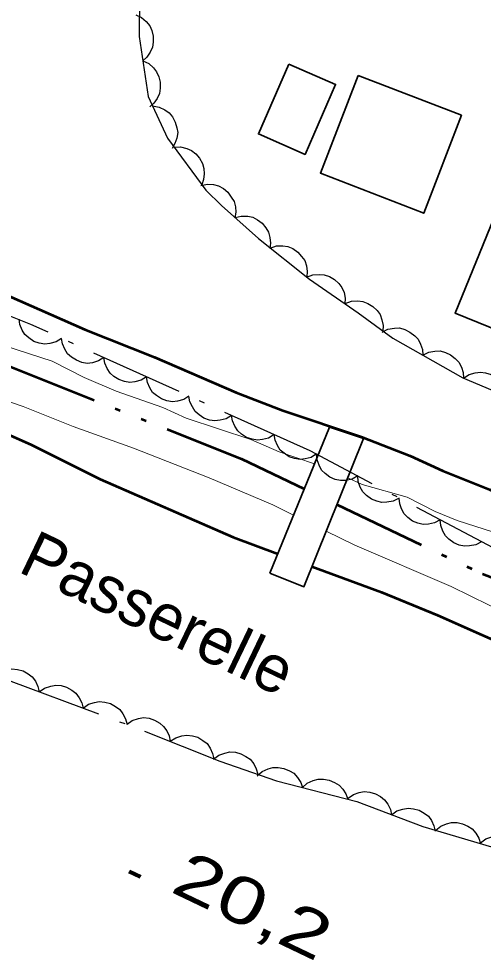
# Model space of a CAD drawing. Extents: x 355726 to 357533, y 5103782 to 5105258.
# Drawn here: x 356605.89 to 356620.8, y 5104468.41 to 5104498.68 of the extents above; entities that cross this region are included whole.
import ezdxf

# ---------------------------------------------------------------- set-up
doc = ezdxf.new("R2010")
doc.units = 0
doc.header["$LTSCALE"] = 0.6
for name, pattern in [('DASH_DOUBLE_DOT', [9.2, 5, -1.2, 0.3, -1.2, 0.3, -1.2]), ('DOT_DASHED', [7.7, 5, -1.2, 0.3, -1.2]), ('LONG_DASHED', [7.5, 6, -1.5])]:
    doc.linetypes.add(name, pattern=pattern)
for name, color, linetype, lineweight in [('1', 7, 'LONG_DASHED', 53), ('2', 7, 'LONG_DASHED', 13), ('26', 7, 'Continuous', 35), ('3', 7, 'Continuous', 140), ('31', 7, 'Continuous', 35), ('4', 7, 'DASH_DOUBLE_DOT', 53), ('44', 7, 'Continuous', 25)]:
    doc.layers.add(name, color=color, linetype=linetype, lineweight=lineweight)

msp = doc.modelspace()

# ---------------------------------------------------------------- linework, layer by layer
at = {"layer": '1', "linetype": 'Continuous'}
for points in [[(356552.78, 5104505.88), (356555.14, 5104504.63), (356555.86, 5104504.34), (356557.38, 5104503.83), (356561.34, 5104502.15), (356564.46, 5104500.97), (356566.07, 5104500.53), (356569.39, 5104499.78), (356570.17, 5104499.58), (356570.87, 5104499.33), (356577.95, 5104496.47), (356580.34, 5104495.65), (356581.96, 5104494.98), (356585.38, 5104493.8), (356587.71, 5104492.76), (356592.19, 5104491.03), (356593.74, 5104490.24), (356595.31, 5104489.51), (356599.4, 5104487.95), (356603.9, 5104486.04), (356606.29, 5104484.98), (356608.5, 5104483.88), (356612.77, 5104482.01), (356614.2, 5104481.48)], [(356586.93, 5104499.7), (356588.36, 5104498.47), (356588.88, 5104498.09), (356591.47, 5104496.68), (356592.2, 5104496.3), (356594.77, 5104495.21), (356597.27, 5104493.88), (356599.92, 5104492.26), (356601.23, 5104491.59), (356604.81, 5104490.09), (356608, 5104488.69), (356610.24, 5104487.8), (356612.87, 5104486.66), (356614.37, 5104486.09)], [(356614.37, 5104486.09), (356616.89, 5104485.24), (356618.46, 5104484.63), (356619.5, 5104484.15), (356621, 5104483.55), (356622.78, 5104482.71)], [(356615.3, 5104481.07), (356617.53, 5104480.24), (356619.33, 5104479.5), (356622.28, 5104478.2), (356623.46, 5104477.61), (356624.92, 5104477), (356626.48, 5104476.13), (356627.3, 5104475.49), (356627.64, 5104475.04), (356627.73, 5104474.76), (356627.72, 5104474.43), (356627.49, 5104473.61), (356626.72, 5104472.08), (356625.59, 5104470.34), (356624.65, 5104469.2), (356624.11, 5104468.62), (356622.87, 5104467.42)]]:
    msp.add_lwpolyline(points, dxfattribs=at)
at = {"layer": '2'}
for points in [[(356615.38, 5104484.37), (356614.25, 5104484.76), (356613.34, 5104485.15), (356611.26, 5104485.84), (356610.51, 5104486.18), (356609.01, 5104486.71), (356607.98, 5104487.15), (356606.96, 5104487.67), (356605.43, 5104488.16), (356603.34, 5104489.12), (356601.96, 5104489.84), (356600.44, 5104490.46), (356599.22, 5104491.03), (356595.18, 5104492.55), (356592.21, 5104494.03), (356589.05, 5104495.28), (356588.17, 5104495.73), (356587.25, 5104496.13)], [(356650.58, 5104495.13), (356648.88, 5104493.63), (356645.97, 5104491.47), (356644.47, 5104490.51), (356643.06, 5104489.53), (356637.5, 5104484.88), (356636.97, 5104484), (356636.63, 5104481.55), (356636.19, 5104480.2), (356635.05, 5104478.25), (356632.25, 5104477.67), (356629.29, 5104479.15), (356628.01, 5104479.68), (356624.56, 5104480.93), (356623.53, 5104481.26), (356621.13, 5104482.17), (356619.97, 5104482.55), (356619.26, 5104482.84), (356618.36, 5104483.3), (356616.91, 5104483.71), (356616.45, 5104483.92)]]:
    msp.add_lwpolyline(points, dxfattribs=at)
at = {"layer": '2', "linetype": 'Continuous'}
for points in [[(356586.39, 5104494.74), (356587.58, 5104494.49), (356588.54, 5104494.21), (356589.2, 5104493.95), (356589.86, 5104493.67), (356591.52, 5104492.84), (356592.94, 5104492.24), (356596.17, 5104490.57), (356598.1, 5104489.63), (356599.96, 5104488.82), (356603.26, 5104487.26), (356604.64, 5104486.69), (356606.02, 5104486.22), (356607.63, 5104485.57), (356609.57, 5104484.88), (356612, 5104483.92), (356614.04, 5104483.05), (356614.71, 5104482.72)], [(356615.76, 5104482.21), (356616.68, 5104481.76), (356619.77, 5104480.43), (356621.6, 5104479.53), (356624.34, 5104478.37), (356626.74, 5104477.11)]]:
    msp.add_lwpolyline(points, dxfattribs=at)
at = {"layer": '26'}
msp.add_lwpolyline([(356613.95, 5104480.86), (356615.86, 5104485.55), (356616.96, 5104485.19), (356615.04, 5104480.42)], close=True, dxfattribs=at)
at = {"layer": '3'}
msp.add_line((356609.43, 5104471.26), (356609.79, 5104471.09), dxfattribs=at)
at = {"layer": '31'}
for points in [[(356614.56, 5104497.22), (356613.58, 5104494.98), (356615.08, 5104494.32), (356616.06, 5104496.57), (356614.56, 5104497.22)], [(356616.78, 5104496.86), (356615.57, 5104493.72), (356618.89, 5104492.43), (356620.1, 5104495.58), (356616.78, 5104496.86)], [(356627.61, 5104493.8), (356624.91, 5104487.18), (356619.9, 5104489.22), (356622.6, 5104495.84), (356627.61, 5104493.8)]]:
    msp.add_lwpolyline(points, close=True, dxfattribs=at)
at = {"layer": '4'}
for points in [[(356565.46, 5104503.29), (356570.55, 5104501.29), (356578.56, 5104498.65), (356585.95, 5104495.66), (356595.51, 5104491.86), (356605.52, 5104487.53), (356613.04, 5104484.53), (356615.05, 5104483.57)], [(356616.1, 5104483.06), (356620.78, 5104480.83), (356625.55, 5104479)]]:
    msp.add_lwpolyline(points, dxfattribs=at)
at = {"layer": '44', "linetype": 'DOT_DASHED'}
for points in [[(356609.76, 5104499.87), (356609.75, 5104498.11), (356610.04, 5104496.18), (356610.66, 5104494.84), (356611.89, 5104493.17), (356612.4, 5104492.68), (356613.58, 5104491.62), (356615.22, 5104490.31), (356616.78, 5104489.23), (356617.9, 5104488.41), (356620.15, 5104487.14), (356621.58, 5104486.53), (356623.03, 5104486.31), (356624.49, 5104486.08), (356626.03, 5104486), (356628.04, 5104486.05), (356629.68, 5104486.5), (356631.05, 5104487.51), (356632.09, 5104488.3), (356633.3, 5104489.39), (356635.14, 5104490.52), (356637.7, 5104492.24), (356642.75, 5104495.89)], [(356601.3, 5104478.99), (356609.92, 5104475.78), (356612.34, 5104474.81), (356614.16, 5104474.18), (356616.74, 5104473.51), (356618.86, 5104472.71), (356621.07, 5104472.06), (356623.04, 5104471.35), (356625.93, 5104470.51), (356626.4, 5104470.64), (356627.44, 5104471.43), (356627.93, 5104471.94), (356628.05, 5104472.85), (356628.03, 5104473.85), (356627.62, 5104474.87), (356627.06, 5104475.97), (356626.33, 5104476.78), (356624.91, 5104477.77), (356623.71, 5104478.45), (356621.32, 5104481.56), (356615.24, 5104484.79), (356606.27, 5104488.85), (356599.99, 5104491.39)]]:
    msp.add_lwpolyline(points, dxfattribs=at)
at = {"layer": '44'}
for points in [[(356609.64, 5104498.81), (356609.83, 5104498.72), (356609.98, 5104498.59), (356610.09, 5104498.46), (356610.16, 5104498.3), (356610.2, 5104498.12), (356610.2, 5104497.93), (356610.18, 5104497.77), (356610.1, 5104497.61), (356610, 5104497.45), (356609.87, 5104497.33)], [(356609.87, 5104497.33), (356610.06, 5104497.24), (356610.21, 5104497.1), (356610.31, 5104496.98), (356610.38, 5104496.82), (356610.42, 5104496.64), (356610.42, 5104496.45), (356610.4, 5104496.28), (356610.33, 5104496.12), (356610.22, 5104495.97), (356610.09, 5104495.85)], [(356610.18, 5104495.88), (356610.39, 5104495.84), (356610.57, 5104495.75), (356610.71, 5104495.66), (356610.82, 5104495.53), (356610.91, 5104495.36), (356610.96, 5104495.18), (356610.99, 5104495.02), (356610.96, 5104494.84), (356610.9, 5104494.67), (356610.81, 5104494.51)], [(356610.87, 5104494.55), (356611.08, 5104494.56), (356611.28, 5104494.51), (356611.43, 5104494.45), (356611.57, 5104494.34), (356611.69, 5104494.2), (356611.78, 5104494.03), (356611.83, 5104493.87), (356611.84, 5104493.7), (356611.82, 5104493.51), (356611.76, 5104493.34)], [(356611.73, 5104493.32), (356611.94, 5104493.36), (356612.14, 5104493.35), (356612.3, 5104493.31), (356612.46, 5104493.22), (356612.6, 5104493.11), (356612.71, 5104492.95), (356612.8, 5104492.81), (356612.84, 5104492.64), (356612.85, 5104492.46), (356612.82, 5104492.28)], [(356612.83, 5104492.29), (356613.03, 5104492.34), (356613.24, 5104492.33), (356613.4, 5104492.3), (356613.55, 5104492.22), (356613.7, 5104492.11), (356613.82, 5104491.96), (356613.91, 5104491.82), (356613.95, 5104491.65), (356613.97, 5104491.47), (356613.95, 5104491.29)], [(356613.96, 5104491.31), (356614.16, 5104491.38), (356614.37, 5104491.38), (356614.53, 5104491.36), (356614.69, 5104491.29), (356614.85, 5104491.18), (356614.97, 5104491.04), (356615.07, 5104490.91), (356615.12, 5104490.74), (356615.15, 5104490.56), (356615.14, 5104490.38)], [(356615.13, 5104490.37), (356615.33, 5104490.45), (356615.53, 5104490.46), (356615.69, 5104490.45), (356615.86, 5104490.39), (356616.02, 5104490.3), (356616.16, 5104490.17), (356616.26, 5104490.04), (356616.33, 5104489.88), (356616.37, 5104489.7), (356616.36, 5104489.52)], [(356616.37, 5104489.53), (356616.57, 5104489.6), (356616.77, 5104489.61), (356616.94, 5104489.59), (356617.1, 5104489.53), (356617.26, 5104489.43), (356617.39, 5104489.3), (356617.49, 5104489.17), (356617.55, 5104489), (356617.59, 5104488.82), (356617.58, 5104488.64)], [(356607.25, 5104488.4), (356607.08, 5104488.29), (356606.88, 5104488.24), (356606.72, 5104488.22), (356606.54, 5104488.25), (356606.37, 5104488.31), (356606.21, 5104488.42), (356606.08, 5104488.53), (356605.99, 5104488.67), (356605.92, 5104488.85), (356605.89, 5104489.02)], [(356617.56, 5104488.6), (356617.74, 5104488.7), (356617.95, 5104488.73), (356618.11, 5104488.74), (356618.28, 5104488.69), (356618.45, 5104488.61), (356618.6, 5104488.49), (356618.71, 5104488.38), (356618.79, 5104488.22), (356618.85, 5104488.05), (356618.86, 5104487.87)], [(356608.62, 5104487.79), (356608.44, 5104487.68), (356608.25, 5104487.62), (356608.08, 5104487.6), (356607.91, 5104487.63), (356607.74, 5104487.7), (356607.58, 5104487.8), (356607.45, 5104487.91), (356607.36, 5104488.06), (356607.29, 5104488.23), (356607.25, 5104488.4)], [(356609.99, 5104487.17), (356609.81, 5104487.06), (356609.61, 5104487.01), (356609.45, 5104486.99), (356609.28, 5104487.02), (356609.1, 5104487.08), (356608.94, 5104487.18), (356608.82, 5104487.29), (356608.72, 5104487.44), (356608.65, 5104487.61), (356608.62, 5104487.79)], [(356618.86, 5104487.87), (356619.05, 5104487.96), (356619.25, 5104487.99), (356619.42, 5104488), (356619.59, 5104487.95), (356619.75, 5104487.88), (356619.9, 5104487.76), (356620.02, 5104487.64), (356620.1, 5104487.48), (356620.16, 5104487.31), (356620.17, 5104487.13)], [(356620.17, 5104487.13), (356620.35, 5104487.24), (356620.54, 5104487.3), (356620.71, 5104487.32), (356620.88, 5104487.3), (356621.06, 5104487.24), (356621.22, 5104487.14), (356621.34, 5104487.04), (356621.44, 5104486.89), (356621.52, 5104486.72), (356621.55, 5104486.54)], [(356611.35, 5104486.55), (356611.18, 5104486.44), (356610.98, 5104486.39), (356610.82, 5104486.37), (356610.64, 5104486.4), (356610.47, 5104486.46), (356610.31, 5104486.57), (356610.18, 5104486.67), (356610.09, 5104486.82), (356610.02, 5104486.99), (356609.99, 5104487.17)], [(356612.72, 5104485.93), (356612.54, 5104485.82), (356612.35, 5104485.77), (356612.18, 5104485.75), (356612.01, 5104485.78), (356611.83, 5104485.84), (356611.68, 5104485.95), (356611.55, 5104486.05), (356611.46, 5104486.2), (356611.38, 5104486.37), (356611.35, 5104486.55)], [(356614.09, 5104485.31), (356613.91, 5104485.2), (356613.71, 5104485.15), (356613.55, 5104485.13), (356613.38, 5104485.16), (356613.2, 5104485.22), (356613.04, 5104485.33), (356612.92, 5104485.43), (356612.82, 5104485.58), (356612.75, 5104485.75), (356612.72, 5104485.93)], [(356615.45, 5104484.69), (356615.28, 5104484.58), (356615.08, 5104484.53), (356614.92, 5104484.51), (356614.74, 5104484.54), (356614.57, 5104484.6), (356614.41, 5104484.71), (356614.28, 5104484.81), (356614.19, 5104484.96), (356614.12, 5104485.13), (356614.09, 5104485.31)], [(356616.77, 5104483.98), (356616.59, 5104483.88), (356616.39, 5104483.84), (356616.22, 5104483.83), (356616.05, 5104483.87), (356615.88, 5104483.94), (356615.73, 5104484.06), (356615.61, 5104484.17), (356615.53, 5104484.33), (356615.47, 5104484.5), (356615.45, 5104484.68)], [(356618.1, 5104483.27), (356617.91, 5104483.17), (356617.71, 5104483.14), (356617.55, 5104483.13), (356617.38, 5104483.17), (356617.21, 5104483.24), (356617.05, 5104483.35), (356616.94, 5104483.47), (356616.85, 5104483.62), (356616.79, 5104483.8), (356616.77, 5104483.98)], [(356619.42, 5104482.57), (356619.24, 5104482.47), (356619.04, 5104482.43), (356618.87, 5104482.42), (356618.7, 5104482.46), (356618.53, 5104482.53), (356618.38, 5104482.65), (356618.26, 5104482.76), (356618.18, 5104482.92), (356618.12, 5104483.09), (356618.1, 5104483.27)], [(356620.75, 5104481.86), (356620.56, 5104481.77), (356620.36, 5104481.73), (356620.2, 5104481.72), (356620.03, 5104481.76), (356619.86, 5104481.83), (356619.7, 5104481.95), (356619.59, 5104482.06), (356619.5, 5104482.21), (356619.44, 5104482.39), (356619.42, 5104482.57)], [(356605.14, 5104477.56), (356605.31, 5104477.68), (356605.5, 5104477.75), (356605.66, 5104477.78), (356605.84, 5104477.76), (356606.02, 5104477.71), (356606.18, 5104477.62), (356606.31, 5104477.52), (356606.42, 5104477.38), (356606.5, 5104477.21), (356606.54, 5104477.04)], [(356606.54, 5104477.04), (356606.71, 5104477.16), (356606.91, 5104477.22), (356607.07, 5104477.25), (356607.24, 5104477.24), (356607.42, 5104477.19), (356607.59, 5104477.09), (356607.72, 5104477), (356607.82, 5104476.85), (356607.91, 5104476.69), (356607.95, 5104476.51)], [(356607.95, 5104476.51), (356608.12, 5104476.64), (356608.31, 5104476.7), (356608.47, 5104476.73), (356608.65, 5104476.71), (356608.83, 5104476.66), (356608.99, 5104476.57), (356609.13, 5104476.47), (356609.23, 5104476.33), (356609.31, 5104476.17), (356609.36, 5104475.99)], [(356609.36, 5104476), (356609.53, 5104476.12), (356609.73, 5104476.18), (356609.89, 5104476.21), (356610.07, 5104476.19), (356610.24, 5104476.13), (356610.41, 5104476.03), (356610.53, 5104475.93), (356610.64, 5104475.79), (356610.71, 5104475.62), (356610.75, 5104475.45)], [(356610.75, 5104475.45), (356610.93, 5104475.56), (356611.12, 5104475.62), (356611.28, 5104475.65), (356611.46, 5104475.63), (356611.63, 5104475.58), (356611.8, 5104475.48), (356611.93, 5104475.38), (356612.03, 5104475.23), (356612.11, 5104475.06), (356612.15, 5104474.89)], [(356612.14, 5104474.88), (356612.31, 5104475), (356612.5, 5104475.07), (356612.66, 5104475.11), (356612.84, 5104475.1), (356613.02, 5104475.05), (356613.18, 5104474.96), (356613.32, 5104474.87), (356613.43, 5104474.73), (356613.51, 5104474.56), (356613.56, 5104474.39)], [(356613.54, 5104474.34), (356613.7, 5104474.48), (356613.89, 5104474.56), (356614.04, 5104474.61), (356614.22, 5104474.61), (356614.4, 5104474.58), (356614.58, 5104474.5), (356614.72, 5104474.42), (356614.84, 5104474.29), (356614.94, 5104474.13), (356615, 5104473.96)], [(356615, 5104473.96), (356615.15, 5104474.1), (356615.34, 5104474.19), (356615.5, 5104474.23), (356615.67, 5104474.23), (356615.85, 5104474.2), (356616.03, 5104474.12), (356616.17, 5104474.04), (356616.29, 5104473.91), (356616.39, 5104473.76), (356616.45, 5104473.59)], [(356616.46, 5104473.62), (356616.63, 5104473.74), (356616.82, 5104473.8), (356616.98, 5104473.83), (356617.16, 5104473.81), (356617.34, 5104473.76), (356617.5, 5104473.67), (356617.63, 5104473.57), (356617.74, 5104473.43), (356617.82, 5104473.26), (356617.86, 5104473.09)], [(356617.86, 5104473.09), (356618.03, 5104473.21), (356618.22, 5104473.27), (356618.39, 5104473.3), (356618.56, 5104473.28), (356618.74, 5104473.23), (356618.91, 5104473.14), (356619.04, 5104473.04), (356619.14, 5104472.9), (356619.22, 5104472.73), (356619.26, 5104472.56)], [(356619.28, 5104472.59), (356619.44, 5104472.72), (356619.62, 5104472.8), (356619.78, 5104472.84), (356619.96, 5104472.84), (356620.14, 5104472.8), (356620.31, 5104472.72), (356620.45, 5104472.63), (356620.56, 5104472.5), (356620.66, 5104472.34), (356620.71, 5104472.16)], [(356620.72, 5104472.19), (356620.89, 5104472.31), (356621.08, 5104472.38), (356621.24, 5104472.41), (356621.42, 5104472.39), (356621.6, 5104472.35), (356621.76, 5104472.25), (356621.9, 5104472.16), (356622, 5104472.02), (356622.09, 5104471.85), (356622.13, 5104471.68)]]:
    msp.add_lwpolyline(points, dxfattribs=at)

# ---------------------------------------------------------------- texts
at = {"layer": '26'}
msp.add_text('Passerelle', height=1.5, rotation=334.422, dxfattribs=at).set_placement((356605.82, 5104480.92))
at = {"layer": '3', "width": 1.35}
msp.add_text('20,2   ', height=1.5, rotation=334.423, dxfattribs=at).set_placement((356610.71, 5104470.63))

doc.saveas('drawing.dxf')
